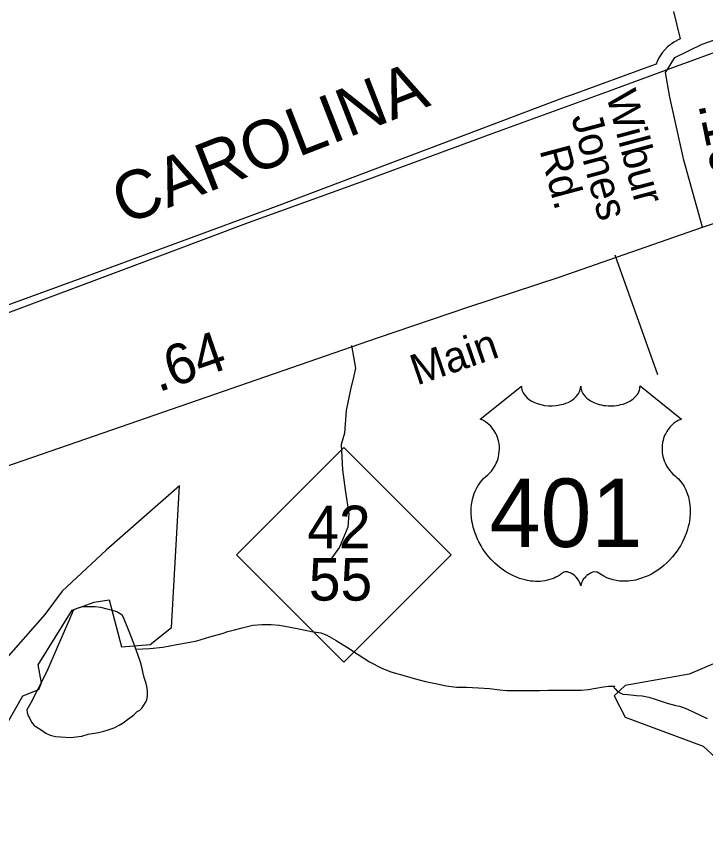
# Model space of a CAD drawing. Extents: x 2001466 to 2224147, y 644118 to 847247.
# Drawn here: x 2068297 to 2070436, y 669883 to 672416 of the extents above; entities that cross this region are included whole.
import ezdxf

# ---------------------------------------------------------------- set-up
doc = ezdxf.new("R2010")
doc.units = 0
for name, color, linetype in [('Exist Boundary Political City Limit New', 7, 'Continuous'), ('Exist Hydrographic Misc Water Feature', 7, 'Continuous'), ('Exist Railroad Mainline', 7, 'Continuous'), ('Exist Railroad Mainline Label', 7, 'Continuous'), ('Exist Road Non-System Type 51', 7, 'Continuous'), ('Exist Road Primary NC Shield CELL', 7, 'Continuous'), ('Exist Road Primary NC Shield Number Label', 7, 'Continuous'), ('Exist Road Primary US Attributed', 7, 'Continuous'), ('Exist Road Primary US Label', 7, 'Continuous'), ('Exist Road Primary US Mileage Hundredths English Label', 7, 'Continuous'), ('Exist Road Primary US Shield CELL', 7, 'Continuous'), ('Exist Road Primary US Shield Number Label', 7, 'Continuous'), ('Exist Road Secondary Mileage Hundredths English Label', 7, 'Continuous'), ('Exist Road Secondary Type 51 Attributed', 7, 'Continuous'), ('Exist Road Secondary Type 51 Label', 7, 'Continuous'), ('Map Preparation Boundary City Limit Buffer Line', 7, 'Continuous')]:
    doc.layers.add(name, color=color, linetype=linetype)

msp = doc.modelspace()

# ---------------------------------------------------------------- linework, layer by layer
at = {"layer": 'Exist Boundary Political City Limit New'}
for points in [[(2070336.6, 672431.8), (2070356.8, 672346.9), (2070336.9, 672336.8), (2070317.4, 672321.8), (2070300.8, 672303.2), (2070290.6, 672287.2), (2070285.4, 672276.2), (2070282.4, 672268.4), (2070264.9, 672262), (2070022.1, 672173.2), (2070000, 672165.1), (2069103.1, 671825.8), (2068496.8, 671603.3), (2068267.1, 671519.3)], [(2068375, 670347.6), (2068364.5, 670404.1), (2068470.1, 670573.4), (2068538.1, 670598.3), (2068584.6, 670605.4), (2068623.1, 670459.9), (2068711.6, 670467), (2068778.1, 670519.4), (2068802.5, 670959.8), (2068575.5, 670760.1), (2068439.2, 670633), (2068384.8, 670560.4), (2068257.6, 670415.1)], [(2068268.8, 670224.1), (2068316.5, 670307.3), (2068366.2, 670327.4), (2068375, 670347.6)]]:
    msp.add_lwpolyline(points, dxfattribs=at)
at = {"layer": 'Exist Hydrographic Misc Water Feature'}
for points in [[(2068667.5, 670452.7), (2068661.6, 670470.6), (2068645.2, 670512.4), (2068629.4, 670550.5), (2068625.1, 670558.5), (2068618.9, 670562.2), (2068608.9, 670568.2), (2068594.7, 670572.4), (2068579, 670576.4), (2068559.1, 670582.3), (2068541, 670584.2), (2068518.9, 670584.3), (2068501, 670584.1), (2068487.3, 670580.2), (2068477.2, 670576), (2068473.1, 670572.1), (2068463.1, 670548.1), (2068423.5, 670458), (2068391.5, 670383.7), (2068363.6, 670328), (2068341.7, 670285.9), (2068329.6, 670263.8), (2068330, 670256), (2068333.7, 670245.7), (2068338, 670237.8), (2068343.6, 670226), (2068351.8, 670215.8), (2068359.7, 670210.1), (2068373.7, 670201.9), (2068387.6, 670192.1), (2068402, 670185.9), (2068417.8, 670181.8), (2068433.8, 670180.2), (2068465.8, 670178.2), (2068481.8, 670180.3), (2068500, 670182.4), (2068519.7, 670188.3), (2068551.7, 670194.4), (2068567.7, 670198.5), (2068582, 670202.4), (2068600.1, 670208.6), (2068615.7, 670216.3), (2068627.8, 670224.3), (2068641.7, 670234.3), (2068655.6, 670244.4), (2068663.4, 670250.5), (2068671.6, 670258.6), (2068679.6, 670262.7), (2068687.6, 670270.7), (2068697.7, 670286.7), (2068701.4, 670294.6), (2068703.8, 670308.4), (2068703.6, 670322.7), (2068701.6, 670336.4), (2068699.5, 670346.4), (2068693.6, 670364.4), (2068689.3, 670382.4), (2068687.6, 670392.4), (2068681.5, 670412.4), (2068673.3, 670436.4), (2068667.5, 670452.7)], [(2068667.5, 670452.7), (2068711.2, 670454.6), (2068751.4, 670458.6), (2068795.1, 670466.6), (2068835.3, 670474.7), (2068857.2, 670478.7), (2068897.4, 670490.8), (2068935.1, 670500.9), (2068953.2, 670507.1), (2068973.3, 670513), (2068997.3, 670519.1), (2069030.9, 670527), (2069059, 670529.2), (2069087.1, 670529.4), (2069112.9, 670527.1), (2069146.9, 670521.2), (2069173, 670515.2), (2069213, 670507.5), (2069241.3, 670503.6), (2069260.7, 670495.8), (2069289, 670479.7), (2069324.9, 670457.7), (2069357.1, 670435.8), (2069393.2, 670413.6), (2069431.1, 670393.7), (2069459.4, 670382.1), (2069503.3, 670370.2), (2069531.4, 670361.9), (2069567.1, 670352), (2069597.2, 670346.2), (2069631.1, 670338.3), (2069663.1, 670334.2), (2069693.4, 670334.5), (2069731.3, 670332.4), (2069765, 670330.5), (2069797.4, 670326.4), (2069819.3, 670324.7), (2069875.3, 670324.7), (2069921.2, 670324.7), (2069947.3, 670324.8), (2069971.5, 670324.8), (2069995.2, 670324.8), (2070029.3, 670324.9), (2070049.4, 670325.2), (2070071.3, 670327.1), (2070094.9, 670331.3), (2070118.9, 670335.3), (2070135.1, 670337.3), (2070153.3, 670337.4)], [(2071069.3, 670102.3), (2071069.3, 670341.8), (2070994.3, 670425.3), (2070835.3, 670408.8), (2070585.2, 670459.9), (2070385.3, 670375.3), (2070186.4, 670340), (2070152.3, 670307.9), (2070186.4, 670241.6), (2070428.3, 670151.4), (2070720.3, 669883), (2070886.2, 669925.5), (2071069.3, 670102.3)], [(2070153.3, 670337.4), (2070150.9, 670333.3), (2070155.4, 670329.4), (2070163, 670321.3), (2070179, 670313.2), (2070193.1, 670311.5), (2070213.2, 670309.3), (2070221.4, 670309.2), (2070238.8, 670307.4), (2070259.6, 670303.5), (2070279.2, 670297.6), (2070317.2, 670285.4), (2070343.2, 670277.8), (2070355.1, 670275.6), (2070367.2, 670271.7), (2070381.6, 670265.5), (2070399.2, 670257.5), (2070419.3, 670247.6), (2070441, 670237.8)]]:
    msp.add_lwpolyline(points, dxfattribs=at)
at = {"layer": 'Exist Railroad Mainline'}
for points in [[(2070333.9, 672257.2), (2070521.1, 672325.7), (2070893.1, 672463.9), (2071265, 672600.2), (2071643.5, 672725.3), (2071820.5, 672759.8), (2071958.3, 672772.3), (2071981.6, 672773.7), (2072001.4, 672775.2), (2072053.4, 672777.4), (2072102.5, 672778.1), (2072146.5, 672778.1), (2072197.1, 672775.2), (2072218.8, 672774.5), (2072287.7, 672771.5)], [(2067171.7, 671081), (2067291.9, 671127.3), (2067513.8, 671213.4), (2067701.8, 671283.5), (2067812.6, 671326.1), (2067889.7, 671355.7), (2068220.9, 671477.9), (2068253.6, 671489.9), (2068637.6, 671634.1), (2069017.5, 671776.4), (2069389.4, 671910.9), (2069773.3, 672053.1), (2070137.2, 672185.3), (2070333.9, 672257.2)]]:
    msp.add_lwpolyline(points, dxfattribs=at)
at = {"layer": 'Exist Road Non-System Type 51'}
msp.add_line((2070154.4, 671676.1), (2070286.9, 671305.4), dxfattribs=at)
for points in [[(2069336.7, 671394.7), (2069349.3, 671324.5), (2069343.8, 671300.8)], [(2069343.8, 671300.8), (2069333.9, 671258.8), (2069320.6, 671193.1), (2069315.2, 671123.2), (2069304.4, 671087.4), (2069308.9, 671009.3), (2069317.6, 670947.1), (2069328.1, 670872.9), (2069325.2, 670831), (2069300, 670769.5), (2069267.1, 670724.2)]]:
    msp.add_lwpolyline(points, dxfattribs=at)
at = {"layer": 'Exist Road Primary NC Shield CELL'}
msp.add_lwpolyline([(2068979.8, 670744.9), (2069312.8, 671077.9), (2069645.8, 670744.9), (2069312.8, 670411.9)], close=True, dxfattribs=at)
at = {"layer": 'Exist Road Primary US Attributed'}
for points in [[(2070426.2, 671762.6), (2070656, 671838), (2071288.5, 672068.2), (2071447.5, 672141.5), (2071586.2, 672222.1)], [(2067248.5, 670668.2), (2067515.3, 670761.4), (2067873.8, 670885), (2068512.2, 671104.9), (2069417.4, 671419.1), (2069697.9, 671513.4), (2069984.6, 671607.6), (2070426.2, 671762.6)]]:
    msp.add_lwpolyline(points, dxfattribs=at)
at = {"layer": 'Exist Road Primary US Shield CELL'}
msp.add_lwpolyline([(2069864.4, 671268.9), (2069864.7, 671263.5), (2069866, 671257.2), (2069867, 671254), (2069870, 671247.7), (2069874.8, 671240.4), (2069881.6, 671233.1), (2069889.3, 671226.8), (2069894.5, 671223.5), (2069903.2, 671218.8), (2069913.2, 671214.6), (2069924.3, 671211.4), (2069935.6, 671209.1), (2069948, 671207.8), (2069960.2, 671207.5), (2069973.4, 671208.5), (2069988, 671211.3), (2069994.7, 671213.1), (2070002.3, 671215.7), (2070009.3, 671218.5), (2070016.9, 671222.6), (2070023.1, 671226.6), (2070027.9, 671230.1), (2070034.7, 671236.6), (2070040.2, 671243.4), (2070042.4, 671247.2), (2070044.4, 671250.8), (2070047.1, 671258.6), (2070047.9, 671262), (2070048.4, 671269.1), (2070048.9, 671263.2), (2070049.5, 671259.4), (2070050.5, 671255.8), (2070052, 671251.9), (2070054.7, 671246.4), (2070057.7, 671241.9), (2070063.5, 671235.1), (2070067, 671231.8), (2070070.3, 671229.1), (2070079, 671223.1), (2070089.3, 671217.9), (2070094.3, 671215.7), (2070099.4, 671213.9), (2070106, 671211.9), (2070112.7, 671210.3), (2070119.4, 671209.2), (2070126.3, 671208.2), (2070133.2, 671207.7), (2070138.9, 671207.5), (2070145.9, 671207.6), (2070152.4, 671208), (2070159, 671208.7), (2070166.3, 671210), (2070172.1, 671211.3), (2070179.9, 671213.3), (2070186.9, 671215.8), (2070193, 671218.5), (2070201, 671222.6), (2070207.4, 671226.7), (2070212.2, 671230.5), (2070217.8, 671235.6), (2070223.1, 671241.8), (2070226.2, 671246.3), (2070228.4, 671250.9), (2070230.5, 671255.8), (2070231.7, 671260.9), (2070232.3, 671265.4), (2070232.4, 671269.3), (2070361, 671166.8), (2070358, 671165.7), (2070351, 671162.2), (2070345.5, 671159), (2070336.6, 671152.7), (2070332.8, 671149.3), (2070329, 671145.7), (2070325.5, 671141.9), (2070322.5, 671138.4), (2070318.7, 671133.2), (2070315.4, 671128), (2070312.1, 671122.3), (2070309.7, 671117.4), (2070305.8, 671107.1), (2070303.9, 671100.5), (2070302.7, 671095), (2070301.2, 671083.5), (2070300.8, 671078), (2070300.8, 671072.6), (2070301.1, 671066.9), (2070301.6, 671061.5), (2070302.6, 671055.8), (2070303.5, 671050.8), (2070305.1, 671044.6), (2070307.4, 671037.5), (2070310.2, 671030.6), (2070316.1, 671019.4), (2070323.6, 671008), (2070329, 671001.6), (2070334.3, 670996.1), (2070342.3, 670989.4), (2070346.6, 670985.6), (2070351.5, 670980.7), (2070359.6, 670971.4), (2070362.8, 670967), (2070366.1, 670962), (2070369.2, 670956.9), (2070372.2, 670951.5), (2070374.6, 670946.7), (2070379.2, 670935.6), (2070382.5, 670924.9), (2070384, 670919.3), (2070386.4, 670906.7), (2070387.3, 670900.5), (2070388.3, 670888.2), (2070388.3, 670873.3), (2070387.2, 670859.1), (2070384.5, 670842.6), (2070382.3, 670832.8), (2070378.9, 670821.3), (2070375.7, 670811.3), (2070369.8, 670796.7), (2070364.6, 670786), (2070357.8, 670773.6), (2070353.2, 670766), (2070347.8, 670758), (2070341, 670748.7), (2070333.1, 670738.8), (2070323.6, 670728.4), (2070316, 670720.8), (2070305.9, 670711.8), (2070299.9, 670706.8), (2070291.2, 670700.2), (2070279.4, 670692.3), (2070267.7, 670685.6), (2070257.7, 670680.5), (2070248.9, 670676.7), (2070237.5, 670672.4), (2070218.5, 670667.1), (2070211.6, 670665.7), (2070203.4, 670664.4), (2070195.7, 670663.7), (2070188.3, 670663.2), (2070178.3, 670663.2), (2070168.3, 670664), (2070158.9, 670665.4), (2070149.1, 670667.4), (2070138.9, 670670.4), (2070129.6, 670674.1), (2070120.1, 670678.7), (2070104.2, 670688.8), (2070099.6, 670691.2), (2070097, 670691.9), (2070090.9, 670692.2), (2070085.1, 670691), (2070079.2, 670688.6), (2070075.6, 670686.7), (2070070.9, 670683.6), (2070067.2, 670680.7), (2070062.8, 670676.5), (2070059.8, 670673), (2070057.5, 670670.3), (2070053, 670663.2), (2070051.4, 670659.9), (2070049.7, 670655.6), (2070048.3, 670649.2), (2070046.2, 670657.2), (2070043.9, 670662.5), (2070041.2, 670667.1), (2070038.3, 670671.1), (2070033.8, 670676.3), (2070029.8, 670680.2), (2070024.9, 670684.1), (2070019.8, 670687.2), (2070015.6, 670689.4), (2070011.8, 670690.8), (2070007.2, 670692), (2070003.4, 670692.3), (2070000.3, 670692.2), (2069996, 670691.2), (2069990.2, 670687), (2069984.7, 670683.2), (2069978.7, 670679.5), (2069971.5, 670675.7), (2069966.3, 670673.3), (2069960.1, 670670.8), (2069952.8, 670668.4), (2069944.9, 670666.3), (2069936.8, 670664.8), (2069929.6, 670663.6), (2069922, 670662.9), (2069915, 670662.7), (2069907.8, 670662.8), (2069901.1, 670663.3), (2069893.2, 670664), (2069883.5, 670665.4), (2069875.5, 670667.3), (2069867, 670669.5), (2069858.2, 670672.3), (2069848.9, 670675.8), (2069837.2, 670680.9), (2069829.1, 670685.1), (2069816.2, 670692.5), (2069801.2, 670702.9), (2069789.8, 670712.1), (2069781.5, 670719.6), (2069769.3, 670732.1), (2069762.1, 670740.2), (2069750.8, 670754.8), (2069743.6, 670765.4), (2069739, 670773.1), (2069732.1, 670785.6), (2069728.4, 670793.4), (2069723.5, 670804.8), (2069719.7, 670815.2), (2069716.5, 670825.1), (2069714.8, 670831.4), (2069712.3, 670842.4), (2069710.9, 670850.2), (2069709.4, 670860.9), (2069708.6, 670872.3), (2069708.5, 670882.7), (2069708.7, 670891.3), (2069709.7, 670901.4), (2069711.4, 670912.2), (2069713.5, 670921.4), (2069715.3, 670928), (2069718.1, 670936), (2069721.7, 670944.9), (2069725.9, 670953.4), (2069730, 670960.5), (2069735.1, 670968.1), (2069740.1, 670974.5), (2069746.7, 670981.7), (2069753.5, 670988.2), (2069759.8, 670993.3), (2069767.2, 671000.6), (2069771.1, 671005), (2069775.8, 671011.2), (2069779.5, 671016.9), (2069782.4, 671022), (2069786.4, 671029.5), (2069788.7, 671035.1), (2069791.7, 671043.8), (2069793.2, 671049.8), (2069794.7, 671057.7), (2069795.7, 671065), (2069796, 671074.2), (2069795.8, 671081.8), (2069794.8, 671090.7), (2069793.2, 671099.2), (2069791.1, 671106.7), (2069788, 671115.2), (2069785, 671121.4), (2069780.1, 671129.9), (2069774.6, 671137.7), (2069769, 671144.1), (2069763.3, 671149.8), (2069757.8, 671154), (2069752.6, 671157.8), (2069746.1, 671161.7), (2069739.8, 671164.8), (2069735.8, 671166.4)], close=True, dxfattribs=at)
at = {"layer": 'Exist Road Secondary Type 51 Attributed'}
for points in [[(2070317.5, 672251.3), (2070340.3, 672289.2), (2070425.5, 672330.3), (2070864.2, 672485), (2071448, 672681.6), (2071971.9, 672866.3), (2072268.5, 672964.2), (2072415.3, 673031.4), (2072577.8, 673164), (2072737.2, 673309.3), (2072781.3, 673391.4), (2072787.7, 673467.2), (2072754.5, 673596.7), (2072710.3, 673786.9)], [(2070426.2, 671762.6), (2070368.7, 671970.2), (2070324.5, 672166), (2070311.9, 672241.8), (2070317.5, 672251.3)]]:
    msp.add_lwpolyline(points, dxfattribs=at)
at = {"layer": 'Map Preparation Boundary City Limit Buffer Line'}
for points in [[(2070336.6, 672431.8), (2070356.8, 672346.9), (2070336.9, 672336.8), (2070317.4, 672321.8), (2070300.8, 672303.2), (2070290.6, 672287.2), (2070285.4, 672276.2), (2070282.4, 672268.4), (2070264.9, 672262), (2070022.1, 672173.2), (2070000, 672165.1), (2069103.1, 671825.8), (2068496.8, 671603.3), (2068267.1, 671519.3)], [(2068375, 670347.6), (2068364.5, 670404.1), (2068470.1, 670573.4), (2068538.1, 670598.3), (2068584.6, 670605.4), (2068623.1, 670459.9), (2068711.6, 670467), (2068778.1, 670519.4), (2068802.5, 670959.8), (2068575.5, 670760.1), (2068439.2, 670633), (2068384.8, 670560.4), (2068257.6, 670415.1)], [(2068268.8, 670224.1), (2068316.5, 670307.3), (2068366.2, 670327.4), (2068375, 670347.6)]]:
    msp.add_lwpolyline(points, dxfattribs=at)

# ---------------------------------------------------------------- texts
at = {"layer": 'Exist Railroad Mainline Label'}
msp.add_text('CAROLINA', height=150, rotation=21.3333, dxfattribs=at).set_placement((2068631.2, 671768))
at = {"layer": 'Exist Road Primary NC Shield Number Label'}
for s, p in [('42', (2069199.4, 670765.4)), ('55', (2069204.3, 670603.2))]:
    msp.add_text(s, height=132.5, dxfattribs=at).set_placement(p)
at = {"layer": 'Exist Road Primary US Label'}
msp.add_text('Main', height=95, rotation=18.9894, dxfattribs=at).set_placement((2069539.8, 671270.6))
at = {"layer": 'Exist Road Primary US Mileage Hundredths English Label'}
msp.add_text('.64', height=125, rotation=19.1399, dxfattribs=at).set_placement((2068737.3, 671249.2))
at = {"layer": 'Exist Road Primary US Shield Number Label'}
msp.add_text('401', height=212.5, dxfattribs=at).set_placement((2069765.6, 670769.6))
at = {"layer": 'Exist Road Secondary Mileage Hundredths English Label'}
msp.add_text('.10', height=125, rotation=281.5585, dxfattribs=at).set_placement((2070412.7, 672143.5))
at = {"layer": 'Exist Road Secondary Type 51 Label'}
for s, p in [('Wilbur', (2070126.4, 672173.3)), (' Jones', (2070009.5, 672138.2)), (' Rd.', (2069910.7, 672035.4))]:
    msp.add_text(s, height=95, rotation=284.9798, dxfattribs=at).set_placement(p)

doc.saveas('drawing.dxf')
